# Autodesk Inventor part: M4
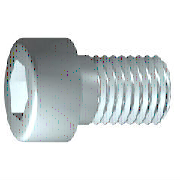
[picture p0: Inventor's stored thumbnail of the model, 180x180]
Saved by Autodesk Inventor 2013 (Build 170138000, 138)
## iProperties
IsCustomPart: 0
Company: 한국ATC센터
Created: 2014-10
Part Number: M4
Material: 강철
Description: 6각머리 태핑 나사
Document SubType Name: Modeling
Standard: KS B 1003
Designer: KYOUNG IL JANG
Standards Organization: KS
Language: ko-KR
Size Designation: M 4 x 10
Categories: <MemberInstance><Categories><Category DisplayName="조임쇠" InternalName="e4da775c-781d-43d5-af7c-5136215cf5a6" Mnemonic="FSTN"><Category DisplayName="볼트" InternalN
Density: 7.85 g/cm^3
Mass: 2.03451 g
Surface Area: 3.0572 cm^2
Volume: 0.259174 cm^3
Author: KYOUNG IL JANG
Revision Number: 1
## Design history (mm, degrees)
sketch "스케치1"
  geometry: L1 (-1, 0)-(10, 0); L2 (10, 0)-(10, 2); L3 (10, 2)-(1.75, 2); L4 (1.75, 2)-(1.32, 2); L5 (1.32, 2)-(0, 2); L6 (0, 2)-(0, 3.5); L7 (0, 3.5)-(-4, 3.5); L8 (-4, 3.5)-(-4, 1.732); L9 (-4, 1.732)-(-2, 1.732); L10 (-2, 1.732)-(-1, 0); L11 (-6.8, 0)-(12.8, 0) reference; L12 (0, -0.7)-(0, 4.2) reference; L13 (1.75, 2)-(0, 2)
  constraints: 22 end point, 6 parallel, 2 collinear, 2 perpendicular, 1 horizontal, 1 point on line
  dimensions: "d1" = 8.25 distance from line of L3.end L2 (= GEL); "d2" = 0.42952 distance of L4.end L3.end (computed from GAL); "d3" = 4 distance between parallel lines of L8 L6 (= KOH); "d4" = 2 distance of L8.end L9.end (= INTI); "d5" = 60 deg angle of L10 L1; "d6" = 4 diameter of L3 L1 (= GD); "d7" = 4 diameter of L5 L1 (= BDM); "d8" = 3.4641 diameter of L9 L1 (= 1.1547 x SW); "d9" = 7 diameter of L7 L1 (= KOD); "d26" = 10 distance between parallel lines of L12 L2 (= NLG)
revolve "본체" sketch "스케치1" stored, may be unused: angle "d10" = 90 deg
sketch "스케치2"
  geometry: L1 (0, -4.9)-(0, 4.9) reference; L2 (-4.9, 0)-(4.9, 0) reference; L3 (1.732, 0)-(0.866, -1.5); L4 (0.866, -1.5)-(-0.866, -1.5); L5 (-0.866, -1.5)-(-1.732, 0); L6 (-1.732, 0)-(-0.866, 1.5); L7 (-0.866, 1.5)-(0.866, 1.5); L8 (0.866, 1.5)-(1.732, 0); 2 further points
  constraints: 12 end point, 1 coincident, 1 horizontal alignment, 1 point on line, 12 other
extrude "슬롯" join sketch "스케치2" stored distance "d11" = 10; taper "d12" = 0 deg
workplane "Work Plane1"
fillet "Fillet2" dims "d30" = 0.1 (= R)
body "Solid1"
fillet "모깎기1" dims "d17" = 0.4 (= RR)
feature "스레드" dims "d13" = 8.25 (= GEL), "d14" = 0
chamfer "모따기1" distance "d15" = 0.42941 (= -0.5 x SPD + 0.5 x GD); stored, may be unused: second distance "d16" = 0.42941 (= GUL), angle "d27" = 45 deg
other parameters: "GD" = 4 (= NND) [user parameter; used in 2 equation terms], "NLG" = 10 [user parameter; used in 1 equation term], "GEL" = 8.25 [user parameter; used in 2 equation terms], "KOD" = 7 [user parameter; used in 1 equation term], "KOH" = 4 [user parameter; used in 1 equation term], "INTI" = 2 [user parameter; used in 1 equation term], "GAL" = 0.42941 (= 0.61345 x PTC) [user parameter; used in 1 equation term], "GUL" = 0.42941 (= 0.61345 x PTC) [user parameter; used in 1 equation term], "BDM" = 4 (= NND) [user parameter; used in 1 equation term], "SW" = 3 [user parameter; used in 2 equation terms], "RR" = 0.4 [user parameter; used in 1 equation term], "SPD" = 3.14117 (= NND - 1.2269 x PTC) [user parameter; used in 1 equation term], "d19" = 0, "d28" = 0, "d29" = 0, "R" = 0.1 [user parameter; used in 1 equation term], "PHH" = 0.2 [user parameter], "GD1" = 3.14117 (= THREADDIA - 1.2269 x PTC) [user parameter], "THREADDIA" = 4 [user parameter; used in 1 equation term], "FAWI" = 45 deg [user parameter], "TPU" = 14.28571 (computed from PTC) [user parameter], "PTC" = 0.7 [user parameter; used in 5 equation terms], "NND" = 4 [user parameter; used in 3 equation terms], "TOA" = 30 deg [user parameter], "E0" = 3.465 (= 1.155 x SW) [user parameter]
